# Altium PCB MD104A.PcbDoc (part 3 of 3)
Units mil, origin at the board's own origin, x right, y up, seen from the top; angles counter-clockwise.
Board outline 3684 x 4279 mil, 4 copper layers (Top Layer, GND Layer, Power Layer, Bottom Layer), stack 61.2 mil thick; 215 components, 107 nets, 500 pads, 726 vias.
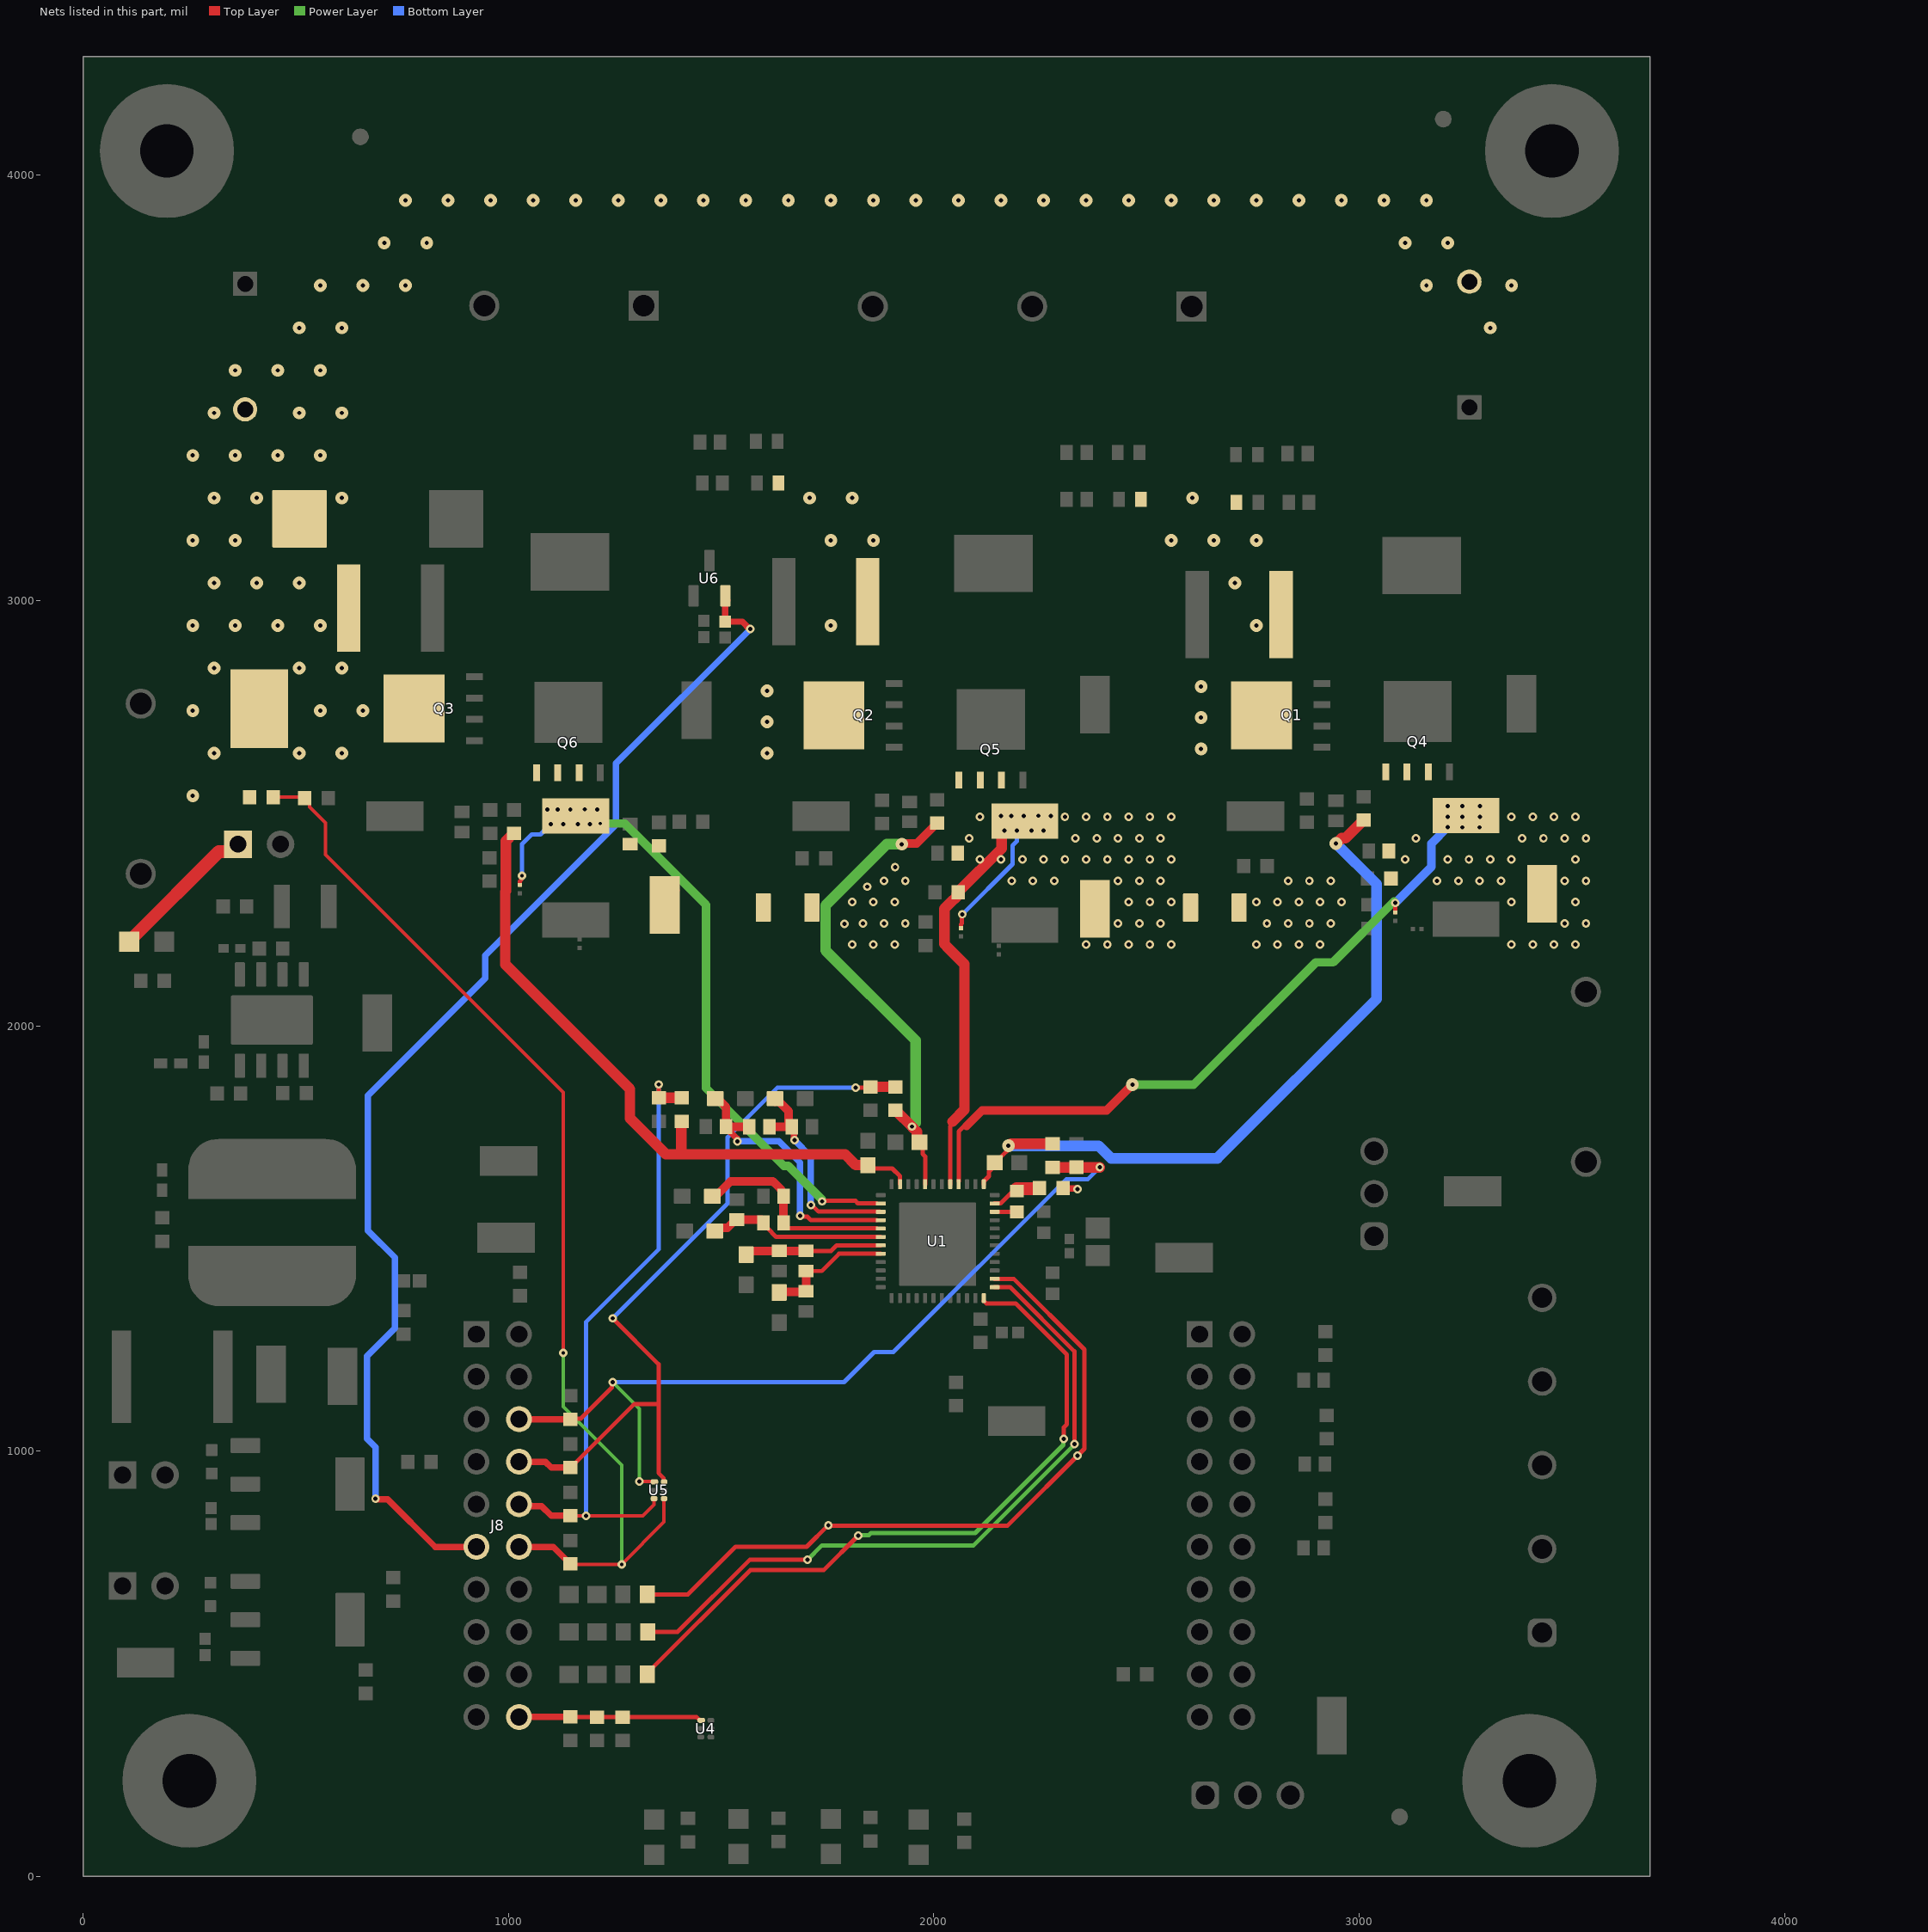
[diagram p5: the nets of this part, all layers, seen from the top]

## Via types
v1: diameter 20/20/20/20 (per signal layer), hole 10, Top Layer to Bottom Layer, tented both sides, 247 vias
v2: diameter 20, hole 10, Top Layer to Bottom Layer, tented both sides, 197 vias
v3: diameter 30, hole 10, Top Layer to Bottom Layer, tented both sides, 161 vias
v4: diameter 20, hole 7.87, Top Layer to Bottom Layer, tented both sides, 56 vias
v5: diameter 30/30/30/30 (per signal layer), hole 10, Top Layer to Bottom Layer, tented both sides, 36 vias
v6: diameter 19.68, hole 7.87, Top Layer to Bottom Layer, tented both sides, 16 vias
v7: diameter 30, hole 7.87, Top Layer to Bottom Layer, tented both sides, 8 vias
v8: diameter 19.68, hole 7.87, Top Layer to Bottom Layer, 4 vias
v9: diameter 20, hole 8, Top Layer to Bottom Layer, tented both sides, 1 vias

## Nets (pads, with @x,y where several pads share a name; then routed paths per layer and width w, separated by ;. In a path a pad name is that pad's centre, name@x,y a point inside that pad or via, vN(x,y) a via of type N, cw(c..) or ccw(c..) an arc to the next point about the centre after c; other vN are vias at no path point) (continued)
SEN_GVDD: C54.2 J8.20 R86.1 R91.2 U4.1 | length 431.5
  Top Layer w10: C54.2@1146,374.88 1146.46,374.42 R91.2@1208.09,374.42 R86.1@1268.33,374.42 1442.75,374.42 1450.22,366.94 U4.1@1453.17,366.94
  Top Layer w15: J8.20@1025,374.88 C54.2@1146,374.88
SEN_VMOTOR: C53.2 J8.12 R65.1 R66.2 U5.4 | length 2638.9
  Top Layer w8: R65.1@446.83,2537.29 518.71,2537.29 532.87,2523.13 532.87,2514.23 570.09,2477.01 570.09,2401.9 1128.99,1843 v4(1128.99,1230.68) ; C53.2@1139.11,740.6 1145.78,733.92 v4(1266.49,733.92) 1365.81,833.24 U5.4@1365.81,888.19
  Top Layer w15: J8.12@1025,774.88 1104.83,774.88 C53.2@1139.11,740.6
  Power Layer w8: v4(1128.99,1230.68) 1128.99,1104.64 1266.49,967.14 v4(1266.49,733.92)
SHA: C6.2 R37.1 R74.2 U1.37 | length 1725.1
  Top Layer w10: U1.37@2117.35,1627.48 2117.35,1634.01 2129.52,1646.18 2129.52,1656.92 2142.47,1669.88 C6.2@2143.39,1669.88 ; C6.2@2143.39,1677.88 2144.31,1677.88 v3@2171.64,1705.21
  Top Layer w25: v3(2175.47,1717.83) 2176.82,1717.83 2181.18,1722.19 R74.2@2279.19,1722.19 ; v3@2945.92,2430 2946.1,2429.83 2947.53,2429.83 2958.58,2440.88 2967.56,2440.88 3005.77,2479.09 3005.77,2480.07 3009.02,2483.32 R37.1@3010,2483.32
  Power Layer w25: v3(2175.47,1717.83) v3@2175.47,1719.18
  Bottom Layer w25: v3(2175.47,1717.83) 2387.27,1717.83 2416.56,1688.54 2666.45,1688.54 3040.74,2062.83 3040.74,2333.35 v3(2945.22,2428.88)
SHB: C7.2 R38.1 R52.2 U1.44 | length 1149.9
  Top Layer w10: C7.2@1973.06,1721 1973.46,1720.6 1973.46,1698.78 1979.55,1692.69 U1.44@1979.55,1627.48
  Top Layer w20: v3(1924.78,2426.92) 1926.69,2428.84 1959.53,2428.84 2007.02,2476.32 R38.1@2008,2476.32
  Top Layer w25: R52.2@1909.85,1801.28 1913.1,1798.03 1913.62,1798.03 v2(1948.64,1763.02) 1948.64,1762.49 1960.24,1750.89 1960.24,1731.33 1965.69,1725.88 C7.2@1966.61,1725.88
  Power Layer w25: v3(1924.78,2426.92) 1889.27,2426.92 1745.5,2283.16 1745.5,2177.24 1957.21,1965.53 1957.21,1771.59 v2(1948.64,1763.02)
SHC: C8.2 R55.2 R56.1 U1.47 | length 1606.9
  Top Layer w10: C8.2@1832.28,1672.65 1843.49,1661.44 C8.2@1859.12,1661.44 ; C8.2@1845,1672.27 1852.84,1664.43 1902.22,1664.43 1920.5,1646.15 U1.47@1920.5,1627.58
  Top Layer w25: R56.1@1013,2452.32 1012.02,2452.32 994.11,2434.41 994.11,2316.89 992.33,2315.11 992.33,2144.32 1285.57,1851.08 1285.57,1782.35 1370.2,1697.72 1406.55,1697.72 ; R55.2@1407,1775.32 1406.55,1774.86 1406.55,1697.72 ; C8.2@1832.28,1672.65 1816.46,1672.65 1791.39,1697.72 1406.55,1697.72
SLA: C27.2 NT4.2 Q4.1 Q4.2 Q4.3 R31.2 R43.1 R76.2 SLA.1 U1.40 | length 1615.6
  Top Layer w8: 2071.96,1764.69 2072.18,1764.47 2076.84,1764.47
  Top Layer w10: U1.40@2058.57,1634.29 2058.57,1751.29 2071.96,1764.69 ; NT4.2@3084.79,2266.41 v2(3084.79,2288.65)
  Top Layer w20: 2076.84,1764.47 2113.05,1800.68 2406.1,1800.68 v3(2466.73,1861.31)
  Power Layer w20: v3(2466.73,1861.31) 2610.35,1861.31 2898.11,2149.07 2938.63,2149.07 v2@3081.5,2291.94
  Bottom Layer w20: v2(3084.79,2288.65) 3170,2373.87 3170,2428.7 v2(3208.14,2466.84)
  other v2: 2758,2190.88 2808,2190.88 2858,2190.88 2908,2190.88 3358,2190.88 3408,2190.88 3458,2190.88 3508,2190.88 2783,2240.88 2833,2240.88 2883,2240.88 2933,2240.88 3483,2240.88 3533,2240.88 2758,2290.88 2808,2290.88 2858,2290.88 2908,2290.88 2958,2290.88 3358,2290.88 3508,2290.88 2833,2340.88 2883,2340.88 2933,2340.88 3183,2340.88 3233,2340.88 3283,2340.88 3333,2340.88 3483,2340.88 3533,2340.88 3108,2390.88 3208,2390.88 3258,2390.88 3308,2390.88 3358,2390.88 3508,2390.88 3133,2440.88 3383,2440.88 3433,2440.88 3483,2440.88 3533,2440.88 3242.64,2466.45 3283.14,2466.45 3358,2490.88 3408,2490.88 3458,2490.88 3508,2490.88 3208.14,2491.55 3242.64,2491.6 3283.67,2491.6 3208.14,2516.55 3242.14,2516.55 3284.14,2516.55
SLB: C28.2 NT5.2 Q5.1 Q5.2 Q5.3 R33.2 R43.2 R44.1 R77.2 SLB.1 U1.41 | length 1263.7
  Top Layer w8: 2038.61,1763.81 2043.67,1768.87
  Top Layer w10: U1.41@2038.61,1627.48 2038.61,1763.81 ; NT5.2@2064,2229.88 2064,2238.75 2066.22,2240.97 2066.22,2261.28 v2(2067.18,2262.24)
  Top Layer w25: 2038.63,2288.84 2024.61,2274.82 2024.61,2192.61 2029.43,2187.37 cw(c2011.81,2169.65) 2029.48,2187.32 2071.97,2144.83 2071.97,1802.56 2044.05,1774.64 ; 2038.63,2288.89 2054.38,2304.63 2054.38,2309.78 2057.62,2313.03 R77.2@2057.62,2314.01 ; R77.2@2057.62,2314.99 2159.36,2416.73 2159.36,2463.69 R33.2@2161.14,2465.47 ; R33.2@2160.36,2466.25 2175.03,2480.93 R33.2@2214,2480.93
  Bottom Layer w10: v2(2067.18,2262.24) 2185.12,2380.18 2185.12,2423.78 2194.97,2433.63 v2(2194.97,2458.65)
  other v2: 1808,2190.88 1858,2190.88 1908,2190.88 2358,2190.88 2408,2190.88 2458,2190.88 2508,2190.88 2558,2190.88 1790.05,2239.87 1833,2240.88 1883,2240.88 1933,2240.88 2433,2240.88 2483,2240.88 2533,2240.88 1808,2290.88 1858,2290.88 1908,2290.88 2458,2290.88 2508,2290.88 2558,2290.88 1843.11,2326.96 1883,2340.88 1933,2340.88 2183,2340.88 2233,2340.88 2283,2340.88 2433,2340.88 2483,2340.88 2533,2340.88 1908.77,2372.89 2108,2390.88 2158,2390.88 2208,2390.88 2258,2390.88 2308,2390.88 2358,2390.88 2408,2390.88 2458,2390.88 2508,2390.88 2558,2390.88 2083,2440.88 2333,2440.88 2383,2440.88 2433,2440.88 2483,2440.88 2533,2440.88 2166.15,2459.25 2229.38,2458.45 2258.2,2458.65 2108,2490.88 2308,2490.88 2358,2490.88 2408,2490.88 2458,2490.88 2508,2490.88 2558,2490.88 2157.96,2493.11 2181.98,2493.11 2211.76,2493.11 2274.81,2493.11 2245.85,2493.73
SLC: C29.2 NT6.2 Q6.1 Q6.2 Q6.3 R44.2 R51.2 R78.2 SLC.1 U1.2 | length 1534
  Top Layer w10: NT6.2@1026.99,2331.06 1026.99,2339.93 1030.08,2343.02 1030.08,2350.68 v4(1031.99,2352.59) ; SLC.1@1367.45,2283.97 1367.45,2287.98 SLC.1@1397.45,2317.98 ; v2(1737.34,1587.12) 1738.47,1588.25 1815.78,1588.25 1821.4,1582.63 U1.2@1865.5,1582.63
  Top Layer w25: R51.2@1173.37,2492.51 v2(1192,2473.88)
  Power Layer w20: v4(1215.84,2475.56) 1273.32,2475.56 1464.46,2284.41 1464.46,1853.32 1647.21,1670.57 1657.93,1670.57 1737.34,1591.17 v2(1737.34,1587.12)
  Bottom Layer w10: v4(1031.99,2352.59) 1031.99,2427.33 1054.62,2449.95 1075.41,2449.95 v2(1099.94,2474.48)
  other v2: 1128.77,2473.88 1163.18,2473.69 1091.76,2508.35 1115.77,2508.35 1145.56,2508.35 1208.6,2508.35 1179.65,2508.96
SNA: C33.2 C48.1 R45.1 U1.4 | length 664.4
  Top Layer w10: v2(1685.58,1552.88) 1687.49,1550.97 1703.08,1550.97 1710.79,1543.26 U1.4@1865.5,1543.26
  Top Layer w15: R45.1@1485.99,1834.68 R45.1@1485.99,1836.65 ; C48.1@1511.55,1763.11 1511.55,1760.16 1537.32,1734.39 1537.32,1729.3 v2(1538.27,1728.35)
  Top Layer w20: R45.1@1485.99,1834.68 1485.99,1830.83 1495.7,1821.12 1499.55,1821.12 1511.55,1809.13 C48.1@1511.55,1763.11 1511.85,1762.81 C33.2@1566.04,1762.81
  Bottom Layer w15: v2(1538.27,1728.35) 1635.82,1728.35 1685.58,1678.59 v2(1685.58,1552.88)
SNB: C41.1 C42.2 R54.1 U1.6 | length 424.4
  Top Layer w10: C42.2@1599.23,1532.94 C42.2@1599.56,1532.94 ; C42.2@1599.56,1536.55 1599.56,1533.6 1619.17,1513.99 1619.17,1513.5 1629.21,1503.46 U1.6@1875.22,1503.46
  Top Layer w20: R54.1@1486.96,1517.16 R54.1@1485,1517.16 1492.71,1524.88 1514.67,1524.88 1534.05,1544.26 C41.1@1537,1544.26 1594.8,1544.26 1599.56,1539.49 C42.2@1599.56,1536.55
SNC: C43.2 C47.1 R53.1 U1.8 | length 304.6
  Top Layer w10: C43.2@1699.83,1423.39 1736.53,1423.39 1777.23,1464.09 U1.8@1875.22,1464.09
  Top Layer w20: R53.1@1636.32,1372.98 1637.65,1374.31 1698.5,1374.31 C47.1@1699.83,1375.64 C43.2@1699.83,1423.39
SOA: R59.2 U1.26 | length 1685.2
  Top Layer w10: R59.2@1325.34,662.94 1422.06,662.94 1533.99,774.88 1701,774.88 v2(1752,825.88) 1753.76,824.12 2172.64,824.12 2353.9,1005.38 2353.9,1238.92 2187.78,1405.03 U1.26@2142.94,1405.03
  other v2: 2338.09,989.57
SOB: R49.2 U1.25 | length 1655.8
  Top Layer w10: R49.2@1326.12,574.88 1397.49,574.88 1567.1,744.48 v2(1703.08,744.48) ; U1.25@2142.94,1385.35 2179.49,1385.35 2330.38,1234.46 v2(2330.38,1016.35)
  Power Layer w10: v2(1703.08,744.48) 1736.97,778.37 2093.5,778.37 2330.38,1015.25 v2(2330.38,1016.35)
SOC: R63.2 U1.24 | length 1663
  Top Layer w10: R63.2@1326.55,478.05 1568.62,720.13 1741.19,720.13 v2(1822.31,801.25) ; U1.24@2117.62,1352.95 2123.36,1347.21 2192.35,1347.21 2312.5,1227.05 2312.5,1062.62 2305.46,1055.58 v2(2305.46,1028.84)
  Power Layer w10: v2(1822.31,801.25) 1823.3,802.24 1847.31,802.24 1852.31,807.24 2097.09,807.24 2304.4,1014.55 2304.4,1027.78 v2(2305.46,1028.84)
SPA: C33.1 C45.1 R11.1 U1.3 | length 513
  Top Layer w10: v2(1710.95,1578.13) 1713.66,1578.13 1728.85,1562.94 U1.3@1872.64,1562.94
  Top Layer w15: R11.1@1626.74,1828.84 R11.1@1628.71,1828.84 ; C45.1@1658.92,1769.77 C45.1@1666.18,1762.5 1671.42,1757.27 1671.42,1732.28 v2(1672.37,1731.32) v2@1672.37,1732.67
  Top Layer w20: C33.1@1616.33,1762.5 C45.1@1665.57,1762.5 ; R11.1@1626.74,1821.12 R11.1@1626.74,1828.84 ; R11.1@1628.71,1828.84 1658.92,1798.63 C45.1@1658.92,1769.77
  Bottom Layer w15: v2(1672.37,1731.32) 1710.95,1692.75 v2(1710.95,1578.13)
SPB: C40.1 C42.1 R32.1 U1.5 | length 485.9
  Top Layer w10: C42.1@1646.8,1536.55 1646.8,1533.6 1656.57,1523.83 1659.52,1523.83 1659.78,1523.57 U1.5@1865.5,1523.57
  Top Layer w20: R32.1@1484.75,1598.79 1486.72,1598.79 1494.43,1606.5 1494.43,1606.69 1522.21,1634.47 1621.55,1634.47 1632.02,1624 1641.86,1614.16 1641.86,1603.64 1646.71,1598.79 1646.71,1536.64 C42.1@1646.8,1536.55
SPC: C43.1 C46.1 R50.1 U1.7 | length 325.9
  Top Layer w10: C43.1@1699.83,1470.63 1758.5,1470.63 1771.64,1483.77 U1.7@1875.22,1483.77
  Top Layer w20: R50.1@1558.88,1462 1558.88,1462.92 1566.59,1470.63 C43.1@1699.83,1470.63
TEMP: C52.1 J8.11 U6.2 | length 2907.7
  Top Layer w15: v2(687.61,887.84) 688.57,886.88 715.6,886.88 827.61,774.88 J8.11@925,774.88 ; C52.1@1509.51,2950.06 1549.8,2950.06 1567.23,2932.63 v2(1568.58,2932.63) ; C52.1@1509.51,2958.77 1509.51,3010.82 U6.2@1509.91,3011.23 ; U6.2@1509.91,3024.6 U6.2@1509.91,3011.23 ; U6.2@1514.23,3000.45 1509.91,3004.76 U6.2@1509.91,3010.82 U6.2@1509.91,3011.23
  Bottom Layer w15: v2(687.61,887.84) 687.61,1009.06 667.22,1029.45 667.22,1223.1 732.77,1288.66 732.77,1455.14 669.88,1518.03 669.88,1835.76 945.43,2111.31 945.43,2165.17 1252.84,2472.58 1252.84,2616.89 v2(1568.58,2932.63)
VCP: C4.2 U1.34 | length 54.8
  Top Layer w10: U1.34@2142.94,1562.51 2143.21,1562.79 2189.89,1562.79 C4.2@2194.64,1567.54
  Top Layer w15: C4.2@2195,1562.2 C4.2@2196.05,1562.2
VDRAIN: C4.1 R39.1 U1.35 | length 118.7
  Top Layer w10: U1.35@2142.94,1582.2 2143.21,1582.48 2157.11,1582.48 2181.58,1606.95 2184.7,1606.95 C4.1@2194.64,1616.89
  Top Layer w30: C4.1@2194.64,1616.89 R39.1@2247.32,1616.89
VMOTOR: C18.1 C20.1 C34.2 C35.2 C44.1 F1.1 J6.1 Q1.5 Q2.5 Q3.5 R25.2 R26.2 R27.2 R39.2 R65.2 VMOTOR.1 VMOTOR_LED.1 | length 387.4
  Top Layer w15: R39.2@2303.56,1619.86 2306.34,1617.08 2337.13,1617.08 v2(2338.09,1616.12)
  Top Layer w30: VMOTOR_LED.1@108.17,2198.44 109.21,2198.44 116.8,2206.03 116.8,2207.06 319.17,2409.44 346.79,2409.44 J6.1@364.27,2426.92
  other v3: 258,2540.88 308,2640.88 508,2640.88 608,2640.88 1608,2640.88 2628.19,2651.28 1608,2714.3 2628.19,2724.71 258,2740.88 558,2740.88 658,2740.88 1608,2787.12 2628.19,2797.52 308,2840.88 508,2840.88 608,2840.88 258,2940.88 358,2940.88 458,2940.88 558,2940.88 1758,2940.88 2758,2940.88 308,3040.88 408,3040.88 508,3040.88 2708,3040.88 258,3140.88 358,3140.88 1758,3140.88 1858,3140.88 2558,3140.88 2658,3140.88 2758,3140.88 308,3240.88 408,3240.88 608,3240.88 1708,3240.88 1808,3240.88 2608,3240.88 258,3340.88 358,3340.88 458,3340.88 558,3340.88 308,3440.88 508,3440.88 608,3440.88 358,3540.88 458,3540.88 558,3540.88 508,3640.88 608,3640.88 3308,3640.88 558,3740.88 658,3740.88 758,3740.88 3158,3740.88 3358,3740.88 708,3840.88 808,3840.88 3108,3840.88 3208,3840.88 758,3940.88 858,3940.88 958,3940.88 1058,3940.88 1158,3940.88 1258,3940.88 1358,3940.88 1458,3940.88 1558,3940.88 1658,3940.88 1758,3940.88 1858,3940.88 1958,3940.88 2058,3940.88 2158,3940.88 2258,3940.88 2358,3940.88 2458,3940.88 2558,3940.88 2658,3940.88 2758,3940.88 2858,3940.88 2958,3940.88 3058,3940.88 3158,3940.88
VSENA: C55.2 J8.6 R74.1 R80.2 U5.1 | length 2022.6
  Top Layer w8: C55.2@1146,1074.88 C55.2@1147.43,1076.31 ; v2@1242.8,1159.77 v2(1245,1161.97) ; v2(1307.86,928.81) 1308.49,928.19 1342.55,928.19 U5.1@1343.17,927.56
  Top Layer w10: C55.2@1147.43,1076.31 1170.05,1076.31 1242.8,1149.06 v2@1242.8,1159.77
  Top Layer w15: J8.6@1025,1074.88 C55.2@1146,1074.88
  Top Layer w25: R74.1@2279.19,1667.08 2279.39,1667.28 2335.35,1667.28 R80.2@2335.55,1667.49 2335.96,1667.08 v2(2389.9,1667.08)
  Power Layer w8: v2(1245,1161.97) 1307.86,1099.11 v2(1307.86,928.81)
  Bottom Layer w10: v2(1245,1161.97) 1788.93,1161.97 1859.71,1232.75 1904.91,1232.75 2311.15,1639 2361.83,1639 v2(2389.9,1667.08)
VSENB: C56.2 J8.8 R52.1 R81.2 U5.6 | length 1811.5
  Top Layer w10: C56.2@1152.89,967.39 1296.38,1110.88 1353.03,1110.88 ; v2(1245,1312.21) 1353.03,1204.18 1353.03,1110.88 ; U5.6@1364.91,926.66 1364.91,936.48 1353.03,948.36 1353.03,1110.88 ; v2(1816.46,1854.21) 1849.18,1854.21 R81.2@1851.37,1856.4
  Top Layer w15: J8.8@1025,974.88 1087.11,974.88 1100.63,961.36 1146.86,961.36 C56.2@1152.89,967.39
  Top Layer w25: R81.2@1851.37,1856.4 R52.1@1909.39,1856.4
  Bottom Layer w10: v2(1245,1312.21) 1515.4,1582.61 1515.4,1737.82 1631.8,1854.21 v2(1816.46,1854.21)
VSENC: C57.2 J8.10 R55.1 R82.2 U5.3 | length 1523.7
  Top Layer w8: C57.2@1146,848.09 1146.38,847.7 v2(1182.19,847.7) 1316.27,847.7 1342.19,873.62 U5.3@1342.19,888.19
  Top Layer w10: R82.2@1353.03,1831.65 v2(1353.03,1862.02)
  Top Layer w15: J8.10@1025,874.88 1029.3,870.58 1078.01,870.58 1100.51,848.09 C57.2@1146,848.09
  Top Layer w25: R82.2@1353.03,1831.65 R82.2@1354.19,1830.49 R55.1@1402.77,1830.46 ; R55.1@1402.79,1830.44 R55.1@1407,1830.44
  Bottom Layer w10: v2(1182.19,847.7) 1182.19,1303.39 1353.03,1474.23 v2(1353.03,1862.02)
pads on no net: C14.2 FID1.1 FID2.1 FID3.1 H1.0 H2.0 H3.0 H4.0 H5.1 H6.1 H7.1 H8.1 J8.3 J8.9 J8.15 J9.6 J9.8 J9.10 J9.18 J9.19 J9.20 SH-J1.0 SH-J2.0 SH-J3.0 SH-J4.0 SH-J5.0 U2.6 U2.9@443.83,2013.41 U4.3 U4.4 U4.6

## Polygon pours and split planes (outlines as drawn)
GND on Power Layer "POWER_LAYER_GND_P068" (solid, remove dead copper, pour order 111): 0,4279 3684,4279 3684,0 0,0
VMOTOR on Power Layer "POWER_LAYER_VMOTOR_P110" (solid, remove dead copper, pour order 110): 334.94,2361.3 409.27,2361.3 409.27,2583.77 2608,2583.77 2608,2181.18 2314.88,1888.06 2314.88,1595.73 2373,1595.73 2373,1859.1 2662.33,2148.44 2662.33,2583.74 3429.63,2583.74 3429.63,3746.18 3079.93,4095.88 827.97,4095.88 184.94,3454.7 184.94,2361.3
SLA on Power Layer "POWER_LAYER_SLA_P086" (solid, remove dead copper, pour order 86): 3578.44,2555.91 3184.32,2555.91 3046,2391.77 2740.52,2391.77 2740.52,2118.88 3578.44,2118.88
SLB on Power Layer "POWER_LAYER_SLB_P078" (solid, remove dead copper, pour order 78): 2560.56,2154.43 2597.01,2190.88 2597.01,2543.3 2037.98,2543.3 1760.52,2278.43 1760.52,2154.43
GND on GND Layer "GND_LAYER_GND_P066" (solid, remove dead copper, pour order 101): 0,4279 3684,4279 3684,0 0,0
MOTC on GND Layer "GND_LAYER_MOTC_P098" (solid, remove dead copper, pour order 98): 1363,3120.88 1485.5,3120.88 1483.67,3301.55 1680.09,3497.96 1921,3497.96 1921,3826.21 1921,3763.88 1545.18,3763.88 980.06,3198.75 980.06,3029.73 868.58,2918.25 868.58,2479.88 1037.06,2479.88 1037.06,2617.01 1363,2628.19
MOTA on GND Layer "GND_LAYER_MOTA_P100" (solid, remove dead copper, pour order 100): 2873.8,2511.88 3043.12,2511.88 3043.12,2628.38 3333,2628.38 3333,3283.54 2840.97,3775.57 2513.5,3775.57 2513.5,3477.57 2873.8,3477.57
MOTB on GND Layer "Top Layer-No Net" (solid, remove dead copper, pour order 99): 2054.08,3765.38 2054.08,3255.96 2050.44,3255.96 1951,3156.88 1951,2968.2 1890.25,2866.3 1856.28,2809.32 1857.33,2618.42 1857.33,2503.26 2035.58,2503.26 2035.58,2609.63 2335.55,2609.63 2335.55,3273.49 2328,3281.04 2328,3402.87 2381.11,3455.98 2391.7,3455.98 2391.69,3765.38
GND on Top Layer "GND_LAYER_GND_P066" (solid, remove dead copper, pour order 128): 0,4279 3684,4279 3684,0 0,0
MOTB on Top Layer "Top Layer-MOTB" (solid, remove dead copper, pour order 121): 2054.08,3765.38 2054.08,3255.96 1973.32,3174.88 1973.32,2990.51 1859.12,2820.28 1859.12,2503.26 2030.06,2503.26 2030.06,2625.32 2335.55,2625.32 2335.55,3390.88 2337.87,3393.19 2372.72,3431.57 2372.72,3765.38
MOTA on Top Layer "TOP_LAYER_MOTA_P122" (solid, remove dead copper, pour order 122): 3033.44,2505.2 3033.44,2638.24 3333,2638.24 3333,3261.88 2831,3763.88 2523,3763.88 2523,3487.77 2857,3487.77 2857,2505.2
MOTC on Top Layer "TOP_LAYER_MOTC_P119" (solid, remove dead copper, pour order 119): 980.06,3015.65 978.44,3203.58 1543.88,3763.88 1921,3763.88 1921,3497.96 1474.88,3497.96 1474.88,3130.88 1363,3130.88 1363,2625.32 1037.06,2625.32 1037.06,2478.11 868,2478.11 868,2920.99
SLC on Top Layer "TOP_LAYER_SLC_P118" (solid, remove dead copper, pour order 118): 1187.75,2618.19 1049.36,2618.19 1049.36,2327.88 1238.19,2327.88 1238.19,2551.98 1187.75,2551.98
SLA on Top Layer "TOP_LAYER_SLA_P108" (solid, remove dead copper, pour order 108): 2851.77,2375.88 2688.04,2375.88 2688.04,2144.83 2973.94,2144.83 2973.94,2375.88
SLB on Top Layer "TOP_LAYER_SLB_P105" (solid, remove dead copper, pour order 105): 1695.53,2230.46 1771.56,2154.43 1959.77,2154.43 1959.77,2394.38 1695.53,2394.38 1695.53,2311.91
VMOTOR on Top Layer "TOP_LAYER_VMOTOR_P093" (solid, pour order 93): 2737.01,3230.15 2737.01,3267.99 2737.01,3294.74 2457,3294.74 2457,3102.15 2673.72,3102.15 2673.72,2843.58 2585,2843.58 2585,2611.97 2847.67,2611.97 2847.67,3230.15
BUCK_OUT on Top Layer "TOP_LAYER_BUCK_OUT_P089" (solid, pour order 89): 154.54,1096.04 82.39,1023.88 32,1023.88 32,636.7 30.69,635.38 49.19,616.88 141,616.88 141,949.96 237.9,1046.86 417.96,1046.86 510.17,1139.07 510.17,1274.88 567.85,1274.88 660.63,1367.66 660.63,1525.89 266.16,1525.89 154.54,1525.89
NetC27_1 on Top Layer "TOP_LAYER_NETC27_1_P129" (solid, pour order 129): 3483.82,3119.49 3332.77,3119.49 3267.1,3185.15 3267.1,3312.08 3499.1,3312.08 3607,3312.08 3607,2629.31 3395.1,2629.31 3395.1,2860.92 3483.82,2860.92
SLA on Top Layer "TOP_LAYER_SLA_P091" (solid, remove dead copper, pour order 91): 3307,2555.84 3561.77,2555.84 3561.77,2156.81 3307,2156.81
VMOTOR on Top Layer "TOP_LAYER_VMOTOR_P092" (solid, remove dead copper, pour order 92): 218.5,2357.44 218.5,2860.06 172.37,2906.19 172.37,3628.88 372,3628.88 812,4068.88 3098,4068.88 3390,3776.88 3390,3605.88 3234.57,3605.88 2964.57,3875.88 929.74,3875.88 678.66,3623.86 678.66,2868.1 851,2868.1 851,2567.75 414.27,2567.75 414.27,2357.44
NetC11_2 on Top Layer "TOP_LAYER_NETC11_2_P102" (solid, pour order 102): 207.65,1636.88 230.94,1613.59 231,1611.88 231,1535.5 669.88,1535.5 669.88,1798.05 599.83,1868.1 599.83,1936.98 598.96,1937.85 497.02,1937.85 497.02,1761.59 495.74,1762.88 231,1762.88 170.41,1702.29 170.41,1636.88
VMOTOR on Top Layer "TOP_LAYER_VMOTOR_P094" (solid, pour order 94): 1696.45,3140.54 1603.85,3140.54 1603.85,3319.96 1886.86,3319.96 1886.86,2894.88 1845.69,2837.73 1845.69,2609.63 1582.36,2609.63 1582.36,2863.87 1696.45,2863.87
NetF1_2 on Top Layer "TOP_LAYER_NETF1_2_P090" (solid, pour order 90): 778.06,3414.53 906.41,3542.88 1061.45,3697.92 1127.41,3763.88 1511.4,3763.88 955.41,3207.88 955.41,3090.88 778.06,3090.88
SLB on Top Layer "TOP_LAYER_SLB_P107" (solid, remove dead copper, pour order 107): 2307.5,2530.82 2629.43,2530.82 2629.43,2169.31 2307.5,2169.31
SLA on Top Layer "TOP_LAYER_SLA_P109" (solid, remove dead copper, pour order 109): 3043.12,2628.38 3040.74,2304.12 3342.59,2300.28 3342.59,2555.91 3184.33,2555.84 3184.33,2628.38
SLB on Top Layer "TOP_LAYER_SLB_P113" (solid, remove dead copper, pour order 113): 2108.37,2604.63 2035.58,2604.63 2035.58,2286.6 2307.5,2286.6 2307.5,2530.8 2182,2530.8 2182,2604.63
SLC on Top Layer "TOP_LAYER_SLC_P104" (solid, remove dead copper, pour order 104): 1230,2450.55 1634.66,2450.55 1634.66,2197.32 1230,2197.32
GND on Bottom Layer "BOTTOM_LAYER_GND_P087" (solid, remove dead copper, pour order 87): 0,4279 3684,4279 3684,0 0,0

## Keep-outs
Keep-Out Layer:
  text ".Layer_Name" at 577,-883.62 h60

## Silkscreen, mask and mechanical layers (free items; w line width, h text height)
Top Overlay:
  circle w12: c848.76,1352.78 r5.51
  circle w12: c2550.97,1339.18 r5.51
  lines w10: 879,315.88 1072.03,314.9 1072.5,315.38 1072.5,1334.38 1072,1334.88 879,1334.88 879,316.88 ; 2577.5,313.9 2770.53,312.93 ; 2577.5,314.9 2577.5,1332.9 2770.5,1332.9 ; 2588.09,133.28 2588.09,104.28 2685.66,104.71 2685.66,133.55 ; 2771,313.4 2771,1332.4 ; 2792.08,138.29 2792.08,108.54 2889.65,108.96 2889.65,138.56 ; 2971.08,1562.49 2950.16,1562.49 2949.79,1647.61 2971.58,1647.61 ; 2971.08,1670.14 2950.16,1670.14 2949.79,1755.25 2971.58,1755.25 ; 2973.36,1542.44 2955.97,1542.44 2948.43,1542.44 2948.83,1451.37 2951.19,1451.37 2949.92,1452.64 2973.8,1452.64
  text "ABS MAX: 30A" at 349,4163.88 h35
  text "MOTC" at 1777.64,3429.42 h35
  text "MOTA" at 2550,3429.42 h35
  text "MOTB" at 2144.92,3429.16 h35
  text "GND" at 894.74,3425.63 h35
  text "VMOTOR" at 1208,3424.88 h35
  text "BUCK_OUT" at 2700.03,1687.04 h30
  text "GVDD" at 2818.74,1588.52 h30
  text "GVDD_EXT" at 2698.01,1481.96 h30
  text "J8" at 879,1361.88 h30
  text "J9" at 2592,1358.88 h30
  text "GND" at 3104,1343.88 h30
  text "HALL_C" at 3011.83,1153.93 h30
  text "HALL_B" at 3011.83,969.05 h30
  text "HALL_A" at 3011.83,770.8 h30
  text "DRV8363-Q1EVM" at 1603.35,744.48 h70
  text "MD104A" at 1603.35,627.27 h70
  text "HALL_PWR" at 2960.24,556.3 h30
  text "HALL" at 2412.14,180.21 h40
  text "PWR" at 2412.14,121.21 h40
  text "SEL" at 2412.14,63.21 h40
  text "3.3V" at 2572,44.88 h40
  text "5V" at 2807.7,44.88 h40
  text ".Layer_Name" at 577,-883.62 h60
Bottom Overlay:
  text ".Layer_Name" at 577,-883.62 h60
Top Paste:
  text ".Layer_Name" at 577,-883.62 h60
Bottom Paste:
  text ".Layer_Name" at 577,-883.62 h60
Top Solder:
  text ".Layer_Name" at 577,-883.62 h60
  text ".Layer_Name" at 577,-883.62 h60
Solder Side:
  text ".Layer_Name" at 577,-883.62 h60
Drill Guide:
  text ".Layer_Name" at 577,-883.62 h60
M1 Board Outline:
  lines w10: 0,0 0,4279 465,4279 3684,4279 3684,0 0,0
  text ".Layer_Name" at 577,-883.62 h60
M2 Board Dimensions:
  rectangle: 0,-300.12 125,-175.12
  rectangle: 125,-425.12 500,-300.12
  lines w7: 0,-300.12 1000,-300.12 ; 125,-425.12 125,-175.12 ; 250,-425.12 250,-175.12 ; 500,-425.12 500,-175.12 ; 750,-425.12 750,-175.12 ; 0,-425.12 1000,-425.12 1000,-175.12 0,-175.12 0,-425.12
  text ".Layer_Name" at 577,-883.62 h60
M3 3D STEP Top:
  text ".Layer_Name" at 577,-883.62 h60
M4 3D STEP Bottom:
  text ".Layer_Name" at 577,-883.62 h60
M5 Assembly Top:
  lines w10: -292,-955.29 6308,-955.29 ; -292,-751.96 6310,-751.96 ; -292,-548.62 -292,-1158.62 3713,-1158.62 6310,-1158.62 6310,-548.62 -291.5,-548.62 -291.5,-1158.62 1284,-1158.62 ; 2173,-1158.62 2173,-548.62 ; 3440,-751.96 3440,-548.62 ; 4280,-751.96 4280,-548.62 ; 4902,-1165.12 4902,-962.29
  text "COMPONENTS MARKED 'DNP' SHOULD NOT BE POPULATED." at 1153.5,-343.62 h60
  text "ASSEMBLY VARIANT:" at 1153,-459.12 h60
  text ".VariantName" at 2189,-459.12 h60
  text "PCB VIEWED FROM TOP SIDE" at -228.5,-680.79 h60
  text "BOARD #:" at 2248,-680.79 h60
  text ".PRJ_Number" at 2793.5,-680.79 h60
  text "REV:" at 3638,-680.79 h60
  text ".PCB_Rev" at 3929.5,-680.79 h60
  text "SVN REV:" at 4476,-680.79 h60
  text ".VersionControl_RevNumber" at 4982,-680.79 h60
  text "TID #:" at 2248,-884.12 h60
  text ".TID" at 2793.5,-884.12 h60
  text "PLOT NAME =" at -228.5,-1089.46 h60
  text ".plot_File_Name" at 577,-1089.46 h60
  text "GENERATED    :" at 2250,-1089.46 h60
  text ".Print_Date" at 3119.5,-1089.46 h60
  text ".Print_Time" at 3848.5,-1089.46 h60
  text "TEXAS INSTRUMENTS" at 5113,-1089.46 h60
M6 Assembly Bottom:
  lines w10: -292.5,-752.46 6309.5,-752.46 ; -290.5,-955.79 6309.5,-955.79 ; 1115.5,-1165.62 1115.5,-962.79 ; 1737.5,-752.46 1737.5,-549.12 ; 2577.5,-752.46 2577.5,-549.12 ; 3844.5,-1159.12 3844.5,-549.12 ; 4733.5,-1159.12 6309,-1159.12 6309,-549.12 -292.5,-549.12 -292.5,-1159.12 2304.5,-1159.12 6309.5,-1159.12 6309.5,-549.12
  text "COMPONENTS MARKED 'DNP' SHOULD NOT BE POPULATED." at 6102,-343.12 h60
  text ".VariantName" at 5058,-459.12 h60
  text "ASSEMBLY VARIANT:" at 6097,-459.12 h60
  text ".VersionControl_RevNumber" at 1035.5,-681.29 h60
  text "SVN REV:" at 1541.5,-681.29 h60
  text ".PCB_Rev" at 2088,-681.29 h60
  text "REV:" at 2379.5,-681.29 h60
  text ".PRJ_Number" at 3224,-681.29 h60
  text "BOARD #:" at 3769.5,-681.29 h60
  text "PCB VIEWED FROM BOTTOM SIDE" at 6246,-681.29 h60
  text ".TID" at 3224,-884.62 h60
  text "TID #:" at 3769.5,-884.62 h60
  text "TEXAS INSTRUMENTS" at 904.5,-1089.96 h60
  text ".Print_Time" at 2169,-1089.96 h60
  text ".Print_Date" at 2898,-1089.96 h60
  text "GENERATED    :" at 3767.5,-1089.96 h60
  text ".plot_File_Name" at 5440.5,-1089.96 h60
  text "PLOT NAME =" at 6246,-1089.96 h60
M9 Title Sheet:
  drawing of 57 lines, arcs and shapes, not listed
  text "1" at 739.84,8011.38 h70
  text "2" at 3235.5,8011.38 h70
  text "3" at 5724.84,8011.38 h70
  text "4" at 8231.51,8011.38 h70
  text "5" at 10730.5,8011.38 h70
  text "6" at 13235.5,8011.38 h70
  text "A" at -416.5,6868.38 h70
  text "A" at 14383.5,6868.38 h70
  text "B" at -416.5,4488.38 h70
  text "B" at 14383.5,4488.38 h70
  text "C" at -416.5,2113.38 h70
  text "C" at 14383.5,2113.38 h70
  text "PROJECT TITLE:" at 11343.5,252.38 h45
  text ".PRJ_Title" at 11393.5,119.05 h70
  text "DESIGNED FOR:" at 11343.5,-48.62 h45
  text ".PRJ_Customer" at 11393.5,-188.62 h70
  text "D" at -416.5,-256.62 h70
  text "D" at 14383.5,-256.62 h70
  text "FILE NAME:" at 11343.5,-348.62 h45
  text ".PCB_File_Name_No_Path" at 11393.5,-468.62 h70
  text "Texas Instruments (TI) and/or its licensors do not warrant the accuracy or completeness of this specification" at 6374,-630.46 h45
  text "ENGINEER:" at 11343.5,-638.62 h45
  text "LAYOUT BY:" at 12848.5,-638.62 h45
  text "or any information contained therein. TI and/or its licensors do not warrant that this design will meet" at 6329.01,-743.13 h45
  text ".PRJ_Engineer" at 11393.5,-793.61 h70
  text ".PCB_Layout" at 12899,-793.61 h70
  text "the specifications, will be suitable for your application or fit for any particular purpose, or will operate in" at 6329.01,-855.79 h45
  text ".Layer_Name" at 577,-883.62 h60
  text "ALTIUM DESIGNER VERSION:" at 12848.5,-948.62 h45
  text "an implementation. TI and/or its licensors do not warrant that the design is production worthy. You should" at 6329.01,-968.46 h45
  text "completely validate and test your design implementation to confirm the system functionality for your application." at 6374,-1081.12 h45
  text ".print_Scale" at 11393.5,-1081.95 h70
  text ".Application_BuildNumber" at 12899,-1081.95 h70
  text "1" at 739.84,-1288.62 h70
  text "2" at 3235.5,-1288.62 h70
  text "3" at 5724.84,-1288.62 h70
  text "4" at 8231.51,-1288.62 h70
  text "5" at 10730.5,-1288.62 h70
  text "6" at 13235.5,-1288.62 h70
M10 Fab Notes:
  drawing of 189 lines, arcs and shapes, not listed
  text "DESIGN INFORMATION" at 12382.02,6331.05 h60
  text "MIN. TRACK WIDTH:" at 11737.46,6198.93 h60
  text "8" at 12833.7,6198.93 h60
  text "MIL" at 12988.46,6198.93 h60
  text "MIN. CLEARANCE:" at 11737.46,6074.8 h60
  text "0.2" at 12773.7,6074.8 h60
  text "mm" at 12988.46,6074.8 h60
  text "MIN. VIA PAD SIZE:" at 11737.46,5950.67 h60
  text "24" at 12803.71,5950.68 h60
  text "MIL" at 12988.46,5950.67 h60
  text "0.05mm (2MIL)" at 12432.46,5820.77 h60
  text "MINIMUM ANNULAR RING" at 11408.23,5812.55 h60
  text "EXTERNAL" at 13140.46,5812.55 h60
  text "PER" at 11608.23,5702.43 h60
  text "IPC-D-275 CLASS 2 LEVEL C" at 11828.23,5702.42 h60
  text "MIL, HOLES" at 13316.46,5601.95 h60
  text "+/-" at 12924,5593.36 h60
  text "+/-" at 13778,5593.36 h60
  text "REGISTRATION TOLERANCES:" at 11408.23,5592.3 h60
  text "METAL" at 12608,5592.3 h60
  text "5" at 13184.2,5592.3 h60
  text "3" at 14017.2,5592.3 h60
  text "MIL" at 14133.46,5592.3 h60
  text "HOLE SIZE TOLERANCE (UNLESS OTHERWISE SPECIFIED):" at 11408.23,5493.98 h60
  text "+/-" at 13778,5491.11 h60
  text "3" at 14017.2,5490.05 h60
  text "MIL" at 14133.46,5490.04 h60
  text "MATERIAL:" at 11333.46,5352.4 h60
  text "FR-4 High Tg" at 12319.9,5223.87 h60
  text "X" at 12175.46,5215.88 h60
  text "FR-408" at 11754.46,5211.37 h60
  text "OTHER" at 13242.46,5211.37 h60
  text "62 MIL (1.6mm) +/-10%" at 12074.56,5068.34 h60
  text "X" at 11954.46,5065.88 h60
  text "THICKNESS:" at 11408.23,5060.12 h60
  text "OTHER" at 13359.46,5060.12 h60
  text "TOLERANCE:" at 11408.23,4921.8 h60
  text "X" at 12256.46,4921.8 h60
  text "ANSI IPC-6012 TYPE 3 CLASS 2" at 12434.48,4921.8 h60
  text "OTHER +/-" at 12434.46,4777.61 h60
  text "BOW & TWIST:" at 11408.23,4632.42 h60
  text "X" at 12256.46,4632.42 h60
  text "ANSI IPC-6012 TYPE 3 CLASS 2" at 12434.48,4632.42 h60
  text "OTHER +/-" at 12434.46,4485.73 h60
  text "DRILLING:" at 11333.46,4355.11 h60
  text "NC_DRILL FILES" at 13094.46,4249.92 h60
  text "REFERENCE:" at 11408.23,4245.98 h60
  text "X" at 12065.46,4245.88 h60
  text "AS SHOWN" at 12243.46,4245.98 h60
  text "X" at 12966.46,4245.98 h60
  text "OTHER" at 13392.46,4103.73 h60
  text "PTH COPPER THICKNESS:" at 11407.91,4100.2 h60
  text "X" at 12547.14,4100.2 h60
  text "20-30 um" at 12675.14,4100.2 h60
  text "BOARD FINISH:" at 11333.46,3952.6 h60
  text "SILKSCREEN:" at 11488.68,3842.48 h60
  text "X" at 12446.46,3842.48 h60
  text "TOP" at 12563.46,3842.48 h60
  text "X" at 12956.46,3842.48 h60
  text "BOTTOM" at 13074.46,3842.48 h60
  text "SILKSCREEN COLOR:" at 11488.68,3687.29 h60
  text "X" at 12445.46,3687.29 h60
  text "WHITE" at 12563.46,3687.29 h60
  text "OTHER" at 13074.46,3687.29 h60
  text "X" at 12576.46,3543.84 h60
  text "GREEN" at 12694.46,3543.84 h60
  text "OTHER" at 13312.46,3543.84 h60
  text "SOLDER RESIST COLOR:" at 11488.68,3536.97 h60
  text "X" at 12576.46,3389.59 h60
  text "MATTE" at 12694.46,3389.59 h60
  text "SEMI-GLOSS" at 13312,3388.95 h60
  text "IMMERSION GOLD (ENIG)" at 12394.46,3216.82 h60
  text "ENEPIG" at 13732,3209.6 h60
  text "SURFACE FINISH:" at 11333.46,3208.6 h60
  text "X" at 12216.46,3208.6 h60
  text "IMM. TIN/SILVER OR EQUIV" at 11663,3071.28 h60
  text "OTHER" at 13094.46,3067.34 h60
  text "ARRAY/PANEL:" at 11333.46,2911.97 h60
  text "CUT AND TRIM PER M1 BOARD OUTLINE" at 12394.46,2903.74 h60
  text "N.C. ROUTE" at 12394.46,2767.78 h60
  text "X" at 13082.46,2767.78 h60
  text "V. SCORE" at 13260.46,2767.78 h60
  text "CERTIFICATION:" at 11333.46,2638.65 h60
  text "MATERIALS AND WORKMANSHIP FOR ALL PCBS" at 12058.46,2638.65 h60
  text "TO MEET OR EXCEED THE REQUIREMENTS OF:" at 12058.46,2544.59 h60
  text "X" at 11695.97,2415.96 h60
  text "ANSI IPC-A-600F CLASS ->" at 11823.96,2415.96 h60
  text "X" at 13471.97,2415.96 h60
  text "2" at 13581.96,2415.96 h60
  text "1" at 13266.96,2414.46 h60
  text "3" at 13935.96,2414.46 h60
  text "X" at 12507.97,2268.27 h60
  text "RoHS" at 12635.96,2268.27 h60
  text "OTHER" at 13280.36,2268.27 h60
  text "PER ORDER" at 13677.42,2268.27 h60
  text "ALL BOARDS MUST MEET OR EXCEED UL94-V0 REQUIREMENTS." at 11361,2114.44 h60
  text "PCB MUST BEAR THE UL94V-0 UL REGISTERED MATERIAL ID NUMBER" at 11361,1998.38 h60
  text "ADDITIONAL REQUIREMENTS:" at 11333.46,1828.96 h60
  text "MICROSECTION:" at 11408.23,1721.83 h60
  text "YES" at 12313.96,1721.83 h60
  text "REQUIRED" at 13175.46,1577.5 h60
  text "BARE BOARD ELEC. TEST:" at 11408.23,1574.64 h60
  text "NONE" at 12713.96,1574.64 h60
  text "X" at 13057.46,1574.64 h60
  text "PER ORDER" at 13767.46,1574.64 h60
  text "XX MIL VIAS REQUIRE NON-CONDUCTIVE FILL AND PLANARIZE" at 11576.38,1369.7 h59
  text "XX MIL VIAS REQUIRE CONDUCTIVE FILL AND PLANARIZE" at 11584.38,1265.72 h60
  text "OUTER XX MIL TRACES REQUIRE 50 OHM SINGLE-ENDED IMPEDANCE" at 11583.39,1102.33 h58
  text "LAYER 2 & 3 (INNER LAYERS) XX MIL WIDE, XX MIL SPACE / TRACES REQUIRE 100 OHM DIFFERENTIAL IMPEDANCE" at 11575.39,866.62 h60
  text ".Layer_Name" at 577,-883.62 h60
M11 Gerber Information:
  lines w10: -292,-955.29 6308,-955.29 ; -292,-751.96 6310,-751.96 ; -292,-548.62 -292,-1158.62 3713,-1158.62 6310,-1158.62 6310,-548.62 -291.5,-548.62 -291.5,-1158.62 1284,-1158.62 ; 2173,-1158.62 2173,-548.62 ; 3440,-751.96 3440,-548.62 ; 4280,-751.96 4280,-548.62 ; 4902,-1165.12 4902,-962.29
  text "ALL ARTWORK VIEWED FROM TOP SIDE" at -228.5,-680.79 h60
  text "BOARD #:" at 2248,-680.79 h60
  text "MD102" at 2793.5,-680.79 h60
  text "REV:" at 3638,-680.79 h60
  text ".PCB_Rev" at 3929.5,-680.79 h60
  text "SVN REV:" at 4476,-680.79 h60
  text ".VersionControl_RevNumber" at 4982,-680.79 h60
  text "LAYER NAME =" at -228.5,-883.62 h60
  text "TID #:" at 2248,-884.12 h60
  text ".TID" at 2793.5,-884.12 h60
  text "PLOT NAME =" at -228.5,-1089.46 h60
  text ".plot_File_Name" at 577,-1089.46 h60
  text "GENERATED    :" at 2250,-1089.46 h60
  text ".Print_Date" at 3119.5,-1089.46 h60
  text ".Print_Time" at 3848.5,-1089.46 h60
  text "TEXAS INSTRUMENTS" at 5113,-1089.46 h60
M12 Stackup:
  drawing of 295 lines, arcs and shapes, not listed
  text "Layer" at 6519.09,7293.38 h60
  text "Name" at 6929,7293.38 h60
  text "Material" at 7858.74,7293.38 h60
  text "Thickness" at 8718.51,7293.38 h60
  text "Constant" at 9368.35,7293.38 h60
  text "Board Layer Stack" at 9938.21,7293.38 h60
  text "Top Overlay" at 6929,7173.38 h60
  text "Top Solder" at 6929,7053.38 h60
  text "Solder Resist" at 7858.74,7053.38 h60
  text "0.40mil" at 8718.51,7053.38 h60
  text "3.5" at 9368.35,7053.38 h60
  text "1" at 6519.09,6933.38 h60
  text "Top Layer" at 6929,6933.38 h60
  text "2.80mil" at 8718.51,6933.38 h60
  text "Dielectric 2" at 6929,6813.38 h60
  text "FR-4 High Tg" at 7858.74,6813.38 h60
  text "10.00mil" at 8718.51,6813.38 h60
  text "4.8" at 9368.35,6813.38 h60
  text "2" at 6519.09,6693.38 h60
  text "GND Layer" at 6929,6693.38 h60
  text "1.40mil" at 8718.51,6693.38 h60
  text "Dielectric 1" at 6929,6573.38 h60
  text "FR-4 High Tg" at 7858.74,6573.38 h60
  text "32.80mil" at 8718.51,6573.38 h60
  text "4.2" at 9368.35,6573.38 h60
  text "3" at 6519.09,6453.38 h60
  text "Power Layer" at 6929,6453.38 h60
  text "1.40mil" at 8718.51,6453.38 h60
  text "Dielectric 3" at 6929,6333.38 h60
  text "FR-4 High Tg" at 7858.74,6333.38 h60
  text "10.00mil" at 8718.51,6333.38 h60
  text "4.8" at 9368.35,6333.38 h60
  text "4" at 6519.09,6213.38 h60
  text "Bottom Layer" at 6929,6213.38 h60
  text "2.80mil" at 8718.51,6213.38 h60
  text "Solder Side" at 6929,6093.38 h60
  text "Solder Resist" at 7858.74,6093.38 h60
  text "0.40mil" at 8718.51,6093.38 h60
  text "3.5" at 9368.35,6093.38 h60
  text "Bottom Overlay" at 6929,5973.38 h60
  text ".Layer_Name" at 577,-883.62 h60
M13 Component Bodies Top:
  text ".Layer_Name" at 577,-883.62 h60
M14 Component Bodies Bottom:
  text ".Layer_Name" at 577,-883.62 h60
M15 Courtyards Top:
  text ".Layer_Name" at 577,-883.62 h60
M16 Courtyards Bottom:
  text ".Layer_Name" at 577,-883.62 h60
Drill Drawing:
  circle w10: c5363.72,3332.84 r16.58
  circle w10: c5363.72,3332.84 r27.63
  circle w10: c5363.72,3208.52 r27.63
  lines w10: 5336.09,2213.96 5363.72,2186.33 5391.34,2213.96 5363.72,2241.59 5336.09,2213.96 ; 5336.09,2310.65 5391.34,2310.65 5391.34,2365.91 5336.09,2365.91 5336.09,2310.65 ; 5336.09,2434.97 5391.34,2434.97 5391.34,2490.23 5336.09,2490.23 5336.09,2434.97 ; 5336.09,2559.29 5336.09,2573.11 5349.9,2586.92 5336.09,2600.73 5336.09,2614.55 5349.9,2614.55 5363.72,2600.73 5377.53,2614.55 5391.34,2614.55 5391.34,2600.73 5377.53,2586.92 5391.34,2573.11 5391.34,2559.29 5377.53,2559.29 5363.72,2573.11 5349.9,2559.29 5336.09,2559.29 ; 5336.09,2683.61 5363.72,2697.43 5391.34,2683.61 5377.53,2711.24 5391.34,2738.87 5363.72,2725.05 5336.09,2738.87 5349.9,2711.24 5336.09,2683.61 ; 5336.09,2821.75 5349.9,2821.75 5349.9,2807.93 5377.53,2807.93 5377.53,2821.75 5391.34,2821.75 5391.34,2849.37 5377.53,2849.37 5377.53,2863.19 5349.9,2863.19 5349.9,2849.37 5336.09,2849.37 5336.09,2821.75 ; 5336.09,2987.51 5391.34,2987.51 5363.72,2932.25 5336.09,2987.51 ; 5336.09,3111.83 5391.34,3111.83 5363.72,3056.57 5336.09,3111.83 ; 5336.09,3429.53 5363.72,3443.35 5391.34,3429.53 5377.53,3457.16 5391.34,3484.79 5363.72,3470.97 5336.09,3484.79 5349.9,3457.16 5336.09,3429.53 ; 5347.14,2446.02 5380.29,2446.02 5380.29,2479.17 5347.14,2479.17 5347.14,2446.02 ; 5347.14,3100.77 5380.29,3100.77 5363.72,3067.62 5347.14,3100.77 ; 5347.14,3440.58 5363.72,3448.87 5380.29,3440.58 5372.01,3457.16 5380.29,3473.73 5363.72,3465.45 5347.14,3473.73 5355.43,3457.16 5347.14,3440.58
  lines w12: 5286,2149.04 8517.49,2149.04 ; 5286,3516.56 8517.49,3516.56 ; 5623.86,2024.72 5623.86,3640.88 ; 5955.86,2024.72 5955.86,3640.88 ; 6592.43,2024.72 6592.43,3640.88 ; 6851.57,2024.72 6851.57,3640.88 ; 7226.72,2024.72 7226.72,3640.88 ; 7951.05,2024.72 7951.05,3640.88 ; 5286,2024.72 8517.49,2024.72 8517.49,3640.88 5286,3640.88 5286,2024.72
  text "Symbol" at 5360.59,3553.85 h72
  text "Quantity" at 5661.16,3553.85 h72
  text "Finished Hole Size" at 5993.16,3553.85 h72
  text "Plated" at 6629.72,3553.85 h72
  text "Hole Type" at 6888.86,3553.85 h72
  text "Drill Layer Pair" at 7264.02,3553.85 h72
  text "Hole Tolerance" at 7988.35,3553.85 h72
  text "84" at 5661.16,3429.53 h60
  text "7.87mil (0.200mm)" at 5993.16,3429.53 h60
  text "PTH" at 6629.72,3429.53 h60
  text "Round" at 6888.86,3429.53 h60
  text "Top Layer - Bottom Layer" at 7264.02,3429.53 h60
  text "1" at 5661.16,3305.21 h60
  text "8.00mil (0.203mm)" at 5993.16,3305.21 h60
  text "PTH" at 6629.72,3305.21 h60
  text "Round" at 6888.86,3305.21 h60
  text "Top Layer - Bottom Layer" at 7264.02,3305.21 h60
  text "641" at 5661.16,3180.89 h60
  text "10.00mil (0.254mm)" at 5993.16,3180.89 h60
  text "PTH" at 6629.72,3180.89 h60
  text "Round" at 6888.86,3180.89 h60
  text "Top Layer - Bottom Layer" at 7264.02,3180.89 h60
  text "4" at 5661.16,3056.57 h60
  text "37.40mil (0.950mm)" at 5993.16,3056.57 h60
  text "PTH" at 6629.72,3056.57 h60
  text "Round" at 6888.86,3056.57 h60
  text "Top Layer - Bottom Layer" at 7264.02,3056.57 h60
  text "6" at 5661.16,2932.25 h60
  text "40.00mil (1.016mm)" at 5993.16,2932.25 h60
  text "PTH" at 6629.72,2932.25 h60
  text "Round" at 6888.86,2932.25 h60
  text "Top Layer - Bottom Layer" at 7264.02,2932.25 h60
  text "40" at 5661.16,2807.93 h60
  text "40.16mil (1.020mm)" at 5993.16,2807.93 h60
  text "PTH" at 6629.72,2807.93 h60
  text "Round" at 6888.86,2807.93 h60
  text "Top Layer - Bottom Layer" at 7264.02,2807.93 h60
  text "6" at 5661.16,2683.61 h60
  text "45.28mil (1.150mm)" at 5993.16,2683.61 h60
  text "PTH" at 6629.72,2683.61 h60
  text "Round" at 6888.86,2683.61 h60
  text "Top Layer - Bottom Layer" at 7264.02,2683.61 h60
  text "5" at 5661.16,2559.29 h60
  text "47.24mil (1.200mm)" at 5993.16,2559.29 h60
  text "PTH" at 6629.72,2559.29 h60
  text "Round" at 6888.86,2559.29 h60
  text "Top Layer - Bottom Layer" at 7264.02,2559.29 h60
  text "5" at 5661.16,2434.97 h60
  text "51.18mil (1.300mm)" at 5993.16,2434.97 h60
  text "PTH" at 6629.72,2434.97 h60
  text "Round" at 6888.86,2434.97 h60
  text "Top Layer - Bottom Layer" at 7264.02,2434.97 h60
  text "+/-3.94mil" at 7988.35,2434.97 h60
  text "4" at 5661.16,2310.65 h60
  text "51.18mil (1.300mm)" at 5993.16,2310.65 h60
  text "PTH" at 6629.72,2310.65 h60
  text "Round" at 6888.86,2310.65 h60
  text "Top Layer - Bottom Layer" at 7264.02,2310.65 h60
  text "4" at 5661.16,2186.33 h60
  text "125.98mil (3.200mm)" at 5993.16,2186.33 h60
  text "PTH" at 6629.72,2186.33 h60
  text "Round" at 6888.86,2186.33 h60
  text "Top Layer - Bottom Layer" at 7264.02,2186.33 h60
  text "800 Total" at 5661.16,2062.01 h60
  text ".Layer_Name" at 577,-883.62 h60
M17 Embedded Cavity:
  text ".Layer_Name" at 577,-883.62 h60
M18 Embedded Assembly:
  text ".Layer_Name" at 577,-883.62 h60
M19 Embedded Keepout:
  text ".Layer_Name" at 577,-883.62 h60

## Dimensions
0,0 to 3684,0 on M2 Board Dimensions
0,-425.12 to 1000,-425.12 on M2 Board Dimensions
0,0 to 0,4279 on M2 Board Dimensions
